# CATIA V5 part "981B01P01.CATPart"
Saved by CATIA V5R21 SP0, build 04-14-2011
Part number: 981B01P01
Bounding box of the stored display mesh (mm): x -33.4 to 33.4, y -100 to 100, z -8 to 8
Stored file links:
  C:\Users\ALI OZGUN\Desktop\alhan\981B01P01.CATPart
  C:\Users\ALI OZGUN\Desktop\alhan\943B01P01.CATPart
  C:\Users\ALI OZGUN\Desktop\alhan\950B01P01.CATPart
  C:\Users\ALI OZGUN\Desktop\alhan\Product1.CATProduct
  C:\Users\ALI OZGUN\Desktop\alhan\954B01P01.CATPart
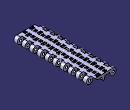
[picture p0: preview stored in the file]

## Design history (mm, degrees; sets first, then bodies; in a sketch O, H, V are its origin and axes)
Body1 (main body)
Body2
  Sketch1 on zx-plane, origin (0, 0, 0), H (-1, 0, 0), V (0, 0, 1)
    construction line L1 (25.4, 8) -> (25.4, -8)
    line L2 (25.4, -8) -> (-25.4, -8)
    construction line L3 (-25.4, -8) -> (-25.4, 8)
    line L4 (-25.4, 8) -> (25.4, 8)
    point P3 (-25.4, -8)
    arc A1 centre (25.4, 0) radius 8 from (25.4, 8) to (25.4, -8) cw
    arc A2 centre (-25.4, 0) radius 8 from (-25.4, 8) to (-25.4, -8) ccw
    point P7 (-25.4, -8)
    length L4 = 50.8
    length L3 = 16
    vertical: L1 V, L3 V
    horizontal: L2 H, L4 H
    equidistance: L1 L3 O, L2 L4 O
    tangency: A1 L2, A2 L4, A2 L2, L4 A1
    coincidence: P7 L2, P3 P7
  Pad1: profile Sketch1, direction (0, 1, 0), length 100, mirrored extent
  Sketch2 on zx-plane, origin (0, 0, 0), H (-1, 0, 0), V (0, 0, 1)
    circle A1 centre (25.4, 0) radius 3.15
    circle A2 centre (-25.4, 0) radius 3.15
  Pocket1: profile Sketch2, direction (0, -1, 0), length 204, mirrored extent
  Body3 "aramesefa"
    Sketch3 on face of Pad1 from Sketch1.L4, origin (0, 0, 8), H (1, 0, 0), V (0, 1, 0)
      line L1 (21.5, -80) -> (55.8232, -80)
      line L2 (55.8232, -80) -> (55.8232, -90.5)
      line L3 (55.8232, -90.5) -> (21.5, -90.5)
      line L4 (21.5, -90.5) -> (21.5, -80)
      reference projected line E1 (-25.4, -100) -> (25.4, -100) from edge [start face of Pad1 | face of Pad1 from Sketch1.L4]
      line L5 (-54.1233, -90) -> (-21.5, -90)
      line L6 (-21.5, -90) -> (-21.5, -100.5)
      line L7 (-21.5, -100.5) -> (-54.1233, -100.5)
      line L8 (-54.1233, -100.5) -> (-54.1233, -90)
      reference projected line E2 (-25.4, -100) -> (25.4, -100) from edge [start face of Pad1 | face of Pad1 from Sketch1.L4]
      distance L1 L3 = 10.5
      distance L3 E1 = 9.5
      distance L4 V = 21.5
      distance L5 L3 = 0.5
      distance L7 E2 = 0.5
      distance L6 L4 = 43
      horizontal: L1 H, L3 H, L5 H, L7 H
      vertical: L2 V, L4 V, L6 V, L8 V
    Pad2: profile Sketch3, direction (0, 0, 1), length 20, mirrored extent
    RectPattern1: of the body so far, direction 1 instances 10, spacing 20, along yz-plane
  Remove1: tool Body3
  Body4 "ALTBOSLUK"
    Sketch4 on zx-plane, origin (0, 0, 0), H (-1, 0, 0), V (0, 0, 1)
      line L1 (48.9583, 0) -> (33.4, 0)
      arc A1 centre (25.4, 0) radius 8 from (17.4, 0) to (33.4, 0) ccw
      line L2 (17.4, 0) -> (17.4, 0.2)
      arc A2 centre (15.4, 0.2) radius 2 from (17.4, 0.2) to (15.4, 2.2) ccw
      line L3 (15.4, 2.2) -> (5.5215, 2.2)
      arc A3 centre (5.5215, 0.2) radius 2 from (5.5215, 2.2) to (3.5325, 0.4091) ccw
      line L4 (3.5325, 0.4091) -> (2.9836, -4.8136)
      arc A4 centre (0, -4.4996) radius 3 from (-2.9836, -4.8136) to (2.9836, -4.8136) ccw
      line L5 (-2.9836, -4.8136) -> (-3.5325, 0.4091)
      arc A5 centre (-5.5215, 0.2) radius 2 from (-3.5325, 0.4091) to (-5.5215, 2.2) ccw
      line L6 (-5.5215, 2.2) -> (-15.4, 2.2)
      arc A6 centre (-15.4, 0.2) radius 2 from (-15.4, 2.2) to (-17.4, 0.2) ccw
      line L7 (-17.4, 0.2) -> (-17.4, 0)
      arc A7 centre (-25.4, 0) radius 8 from (-33.4, 0) to (-17.4, 0) ccw
      line L8 (-33.4, 0) -> (-46.3888, 0)
      line L9 (-46.3888, 0) -> (-46.3888, -17.807)
      line L10 (-46.3888, -17.807) -> (48.9583, -17.807)
      line L11 (48.9583, -17.807) -> (48.9583, 0)
      vertical: L9 V, L11 V
      horizontal: L10 H
    Pad3: profile Sketch4, direction (0, 1, 0), length 215, mirrored extent
  Remove2: tool Body4
  Body5 "KALANTIBOSALTMA"
    Sketch5 on face of Pad1 from Sketch1.L4, origin (0, 0, 8), H (1, 0, 0), V (0, 1, 0)
      line L1 (10, -80) -> (55.8232, -80)
      line L2 (55.8232, -80) -> (55.8232, -90.5)
      line L3 (55.8232, -90.5) -> (10, -90.5)
      line L4 (10, -90.5) -> (10, -80)
      reference projected line E1 (-25.4, -100) -> (25.4, -100) from edge [start face of Pad1 | face of Pad1 from Sketch1.L4]
      line L5 (-54.1233, -90) -> (-10, -90)
      line L6 (-10, -90) -> (-10, -100.5)
      line L7 (-10, -100.5) -> (-54.1233, -100.5)
      line L8 (-54.1233, -100.5) -> (-54.1233, -90)
      reference projected line E2 (-25.4, -100) -> (25.4, -100) from edge [start face of Pad1 | face of Pad1 from Sketch1.L4]
      distance L1 L3 = 10.5
      distance L3 E1 = 9.5
      distance L4 V = 10
      distance L5 L3 = 0.5
      distance L7 E2 = 0.5
      distance L6 L4 = 20
      horizontal: L1 H, L3 H, L5 H, L7 H
      vertical: L2 V, L4 V, L6 V, L8 V
    Pad4: profile Sketch5, direction (0, 0, 1), length 20, mirrored extent
    RectPattern2: of the body so far, direction 1 instances 10, spacing 20, along yz-plane
    Sketch6 on zx-plane, origin (0, 0, 0), H (-1, 0, 0), V (0, 0, 1)
      line L1 (108.0577, 2.2) -> (-84.5523, 2.2)
      fix: L1
    Pocket2: profile Sketch6, direction (0, -1, 0), length 215, mirrored extent
  Remove3: tool Body5
  Body6 "aramesefa ACILARI"
    Sketch7 on face of Pad1 from Sketch1.L4, origin (0, 0, 8), H (1, 0, 0), V (0, 1, 0)
      line L1 (21.5, -80) -> (55.8232, -80)
      line L2 (55.8232, -80) -> (55.8232, -90.5)
      line L3 (55.8232, -90.5) -> (21.5, -90.5)
      line L4 (21.5, -90.5) -> (21.5, -80)
      reference projected line E1 (-25.4, -100) -> (25.4, -100) from edge [start face of Pad1 | face of Pad1 from Sketch1.L4]
      line L5 (-54.1233, -90) -> (-21.5, -90)
      line L6 (-21.5, -90) -> (-21.5, -100.5)
      line L7 (-21.5, -100.5) -> (-54.1233, -100.5)
      line L8 (-54.1233, -100.5) -> (-54.1233, -90)
      reference projected line E2 (-25.4, -100) -> (25.4, -100) from edge [start face of Pad1 | face of Pad1 from Sketch1.L4]
      distance L1 L3 = 10.5
      distance L3 E1 = 9.5
      distance L4 V = 21.5
      distance L5 L3 = 0.5
      distance L7 E2 = 0.5
      distance L6 L4 = 43
      horizontal: L1 H, L3 H, L5 H, L7 H
      vertical: L2 V, L4 V, L6 V, L8 V
    Pad5: profile Sketch7, direction (0, 0, 1), length 20, mirrored extent
    Sketch8 on zx-plane, origin (0, 0, 0), H (-1, 0, 0), V (0, 0, 1)
      line L1 (67.6223, 8) -> (-70.015, 8)
      fix: L1
    Pocket3: profile Sketch8, direction (0, -1, 0), length 215, mirrored extent
    Draft1: Angle 45, Neutral face of Pocket3 from Sketch8.L1, PullDir face of Pocket3 from Sketch8.L1, SupportToDraft face of Pad5 from Sketch7.L6
    Draft2: Angle 45, Neutral face of Pocket3 from Sketch8.L1, PullDir face of Pocket3 from Sketch8.L1, SupportToDraft face of Pad5 from Sketch7.L4
    RectPattern3: of the body so far, direction 1 instances 10, spacing 20, along yz-plane
  Remove4: tool Body6
  Body7
    Sketch9, origin (0, 0, 8), H (1, 0, 0), V (0, 1, 0)
      construction line L1 (-5.5, 96.9) -> (-14.2, 96.9)
      point P1 (-5.5, 96.9)
      point P2 (-14.2, 96.9)
      line L2 (-5.5, 98.05) -> (-14.2, 98.05)
      line L3 (-14.2, 95.75) -> (-5.5, 95.75)
      arc A1 centre (-14.2, 96.9) radius 1.15 from (-14.2, 98.05) to (-14.2, 95.75) ccw
      arc A2 centre (-5.5, 96.9) radius 1.15 from (-5.5, 95.75) to (-5.5, 98.05) ccw
      point P3 (-5.5, 98.05)
      point P4 (-14.2, 98.05)
      point P5 (-14.2, 95.75)
      point P6 (-5.5, 95.75)
      construction line L4 (-5.5, 92.6) -> (-14.2, 92.6)
      point P7 (-5.5, 92.6)
      point P8 (-14.2, 92.6)
      line L5 (-5.5, 93.75) -> (-14.2, 93.75)
      line L6 (-14.2, 91.45) -> (-5.5, 91.45)
      arc A3 centre (-14.2, 92.6) radius 1.15 from (-14.2, 93.75) to (-14.2, 91.45) ccw
      arc A4 centre (-5.5, 92.6) radius 1.15 from (-5.5, 91.45) to (-5.5, 93.75) ccw
      point P9 (-5.5, 93.75)
      point P10 (-14.2, 93.75)
      point P11 (-14.2, 91.45)
      point P12 (-5.5, 91.45)
      construction line L7 (11.2, 96.9) -> (5.5, 96.9)
      point P13 (11.2, 96.9)
      point P14 (5.5, 96.9)
      line L8 (11.2, 98.05) -> (5.5, 98.05)
      line L9 (5.5, 95.75) -> (11.2, 95.75)
      arc A5 centre (5.5, 96.9) radius 1.15 from (5.5, 98.05) to (5.5, 95.75) ccw
      arc A6 centre (11.2, 96.9) radius 1.15 from (11.2, 95.75) to (11.2, 98.05) ccw
      point P15 (11.2, 98.05)
      point P16 (5.5, 98.05)
      point P17 (5.5, 95.75)
      point P18 (11.2, 95.75)
      construction line L10 (11.2, 92.6) -> (5.5, 92.6)
      point P19 (11.2, 92.6)
      point P20 (5.5, 92.6)
      line L11 (11.2, 93.75) -> (5.5, 93.75)
      line L12 (5.5, 91.45) -> (11.2, 91.45)
      arc A7 centre (5.5, 92.6) radius 1.15 from (5.5, 93.75) to (5.5, 91.45) ccw
      arc A8 centre (11.2, 92.6) radius 1.15 from (11.2, 91.45) to (11.2, 93.75) ccw
      point P21 (11.2, 93.75)
      point P22 (5.5, 93.75)
      point P23 (5.5, 91.45)
      point P24 (11.2, 91.45)
      construction line L13 (0, 140.1223) -> (0, 109.3492)
      point P27 (14.2, 82.6)
      point P28 (5.5, 82.6)
      construction line L14 (5.5, 82.6) -> (14.2, 82.6)
      point P29 (5.5, 81.45)
      point P30 (14.2, 81.45)
      point P31 (14.2, 83.75)
      point P32 (5.5, 83.75)
      point P33 (14.2, 86.9)
      point P34 (5.5, 86.9)
      construction line L15 (5.5, 86.9) -> (14.2, 86.9)
      point P35 (5.5, 85.75)
      point P36 (14.2, 85.75)
      point P37 (14.2, 88.05)
      point P38 (5.5, 88.05)
      point P39 (-5.5, 82.6)
      point P40 (-11.2, 82.6)
      construction line L16 (-11.2, 82.6) -> (-5.5, 82.6)
      point P41 (-11.2, 81.45)
      point P42 (-5.5, 81.45)
      point P43 (-5.5, 83.75)
      point P44 (-11.2, 83.75)
      point P45 (-5.5, 86.9)
      point P46 (-11.2, 86.9)
      construction line L17 (-11.2, 86.9) -> (-5.5, 86.9)
      point P47 (-11.2, 85.75)
      point P48 (-5.5, 85.75)
      point P49 (-5.5, 88.05)
      point P50 (-11.2, 88.05)
      line L18 (5.5, 81.45) -> (14.2, 81.45)
      line L19 (14.2, 83.75) -> (5.5, 83.75)
      arc A9 centre (14.2, 82.6) radius 1.15 from (14.2, 81.45) to (14.2, 83.75) ccw
      arc A10 centre (5.5, 82.6) radius 1.15 from (5.5, 83.75) to (5.5, 81.45) ccw
      line L20 (5.5, 85.75) -> (14.2, 85.75)
      line L21 (14.2, 88.05) -> (5.5, 88.05)
      arc A11 centre (14.2, 86.9) radius 1.15 from (14.2, 85.75) to (14.2, 88.05) ccw
      arc A12 centre (5.5, 86.9) radius 1.15 from (5.5, 88.05) to (5.5, 85.75) ccw
      line L22 (-11.2, 81.45) -> (-5.5, 81.45)
      line L23 (-5.5, 83.75) -> (-11.2, 83.75)
      arc A13 centre (-5.5, 82.6) radius 1.15 from (-5.5, 81.45) to (-5.5, 83.75) ccw
      arc A14 centre (-11.2, 82.6) radius 1.15 from (-11.2, 83.75) to (-11.2, 81.45) ccw
      line L24 (-11.2, 85.75) -> (-5.5, 85.75)
      line L25 (-5.5, 88.05) -> (-11.2, 88.05)
      arc A15 centre (-5.5, 86.9) radius 1.15 from (-5.5, 85.75) to (-5.5, 88.05) ccw
      arc A16 centre (-11.2, 86.9) radius 1.15 from (-11.2, 88.05) to (-11.2, 85.75) ccw
      construction line L26 (5.5, 82.6) -> (5.5, 62.21)
      axis line L27 (-5.5, 82.6) -> (-5.5, 59.0476)
      radius A11 = 1.15
      radius A9 = 1.15
      radius A6 = 1.15
      radius A8 = 1.15
      distance L3 L5 = 2
      distance L6 L25 = 3.4
      distance P31 P36 = 2
      distance P43 P48 = 2
      distance A2 A1 = 11
      distance A5 A6 = 8
      distance L14 H = 82.6
      distance L26 V = 5.5
      distance L27 V = 5.5
      distance A16 A15 = 8
      distance P46 P40 H = 0
      distance P8 P2 H = 0
      distance A10 A9 = 11
      distance P19 P13 H = 0
      horizontal: L25 H, L24 H, L23 H, L22 H, L21 H, L20 H, L19 H, L18 H, L12 H, L11 H, L9 H, L8 H, L6 H, L5 H, L3 H, L2 H, L17 H, L16 H, L15 H, L14 H, L10 H, L7 H, L4 H, L1 H
      coincidence: L1 L7, L1 P13, L1 P14, P1 L7, P2 L7, P3 L8, P4 L8, P5 L9, P6 L9, L4 L10, L4 P19, L4 P20, P7 L10, P8 L10, P9 L11, P10 L11, P11 L12, P12 L12, P15 L2, P16 L2, P17 L3, P18 L3, P21 L5, P22 L5, P23 L6, P24 L6, P27 L16, P28 L16, L14 P39, L14 P40, L14 L16, P29 L22, P30 L22, P31 L23, P32 L23, P33 L17, P34 L17, L15 P45, L15 P46, L15 L17, P35 L24, P36 L24, P37 L25, P38 L25, P41 L18, P42 L18, P43 L19, P44 L19, P47 L20, P48 L20, P49 L21, P50 L21, L2 L8, L3 L9, L5 L11, L6 L12, L18 L22, L19 L23, L20 L24, L21 L25, P34 L26, P20 L26, P14 L26, P45 L27, P7 L27, P1 L27
      tangency: L2 A1, L2 A2, L2 A5, L2 A6, L3 A1, L3 A2, L3 A5, L3 A6, A1 L8, A1 L9, A2 L8, A2 L9, L5 A3, L5 A4, L5 A7, L5 A8, L6 A3, L6 A4, L6 A7, L6 A8, A3 L11, A3 L12, A4 L11, A4 L12, L8 A5, L8 A6, L9 A5, L9 A6, L11 A7, L11 A8, L12 A7, L12 A8, L18 A9, L18 A10, L18 A13, L18 A14, L19 A9, L19 A10, L19 A13, L19 A14, A9 L22, A9 L23, A10 L22, A10 L23, L20 A11, L20 A12, L20 A15, L20 A16, L21 A11, L21 A12, L21 A15, L21 A16, A11 L24, A11 L25, A12 L24, A12 L25, L22 A13, L22 A14, L23 A13, L23 A14, L24 A15, L24 A16, L25 A15, L25 A16
      vertical: L26 V, L27 V
    Pad6: profile Sketch9, direction (0, 0, 1), length 10, mirrored extent
    RectPattern4: of the body so far, direction 1 instances 10, spacing 20, along yz-plane reversed
    Symmetry1: ToTransfor RectPattern4, Reference yz-plane
  Remove5: tool Body7
  Sketch10 on zx-plane, origin (0, 0, 0), H (-1, 0, 0), V (0, 0, 1)
    line L1 (0, 72) -> (0, 6.9718)
    point P1 (0, 72)
    reference projected line E1 (-25.4, -8) -> (25.4, -8) from edge [face of Pad1 from Sketch1.L2 | end face of Pad1]
    distance P1 E1 = 80
    coincidence: P1 V
    vertical: L1 V
Body8
  Solid1: linked copy from another document
  Translate1: Direction yz-plane, Length 50.8, ToTransfor Solid1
